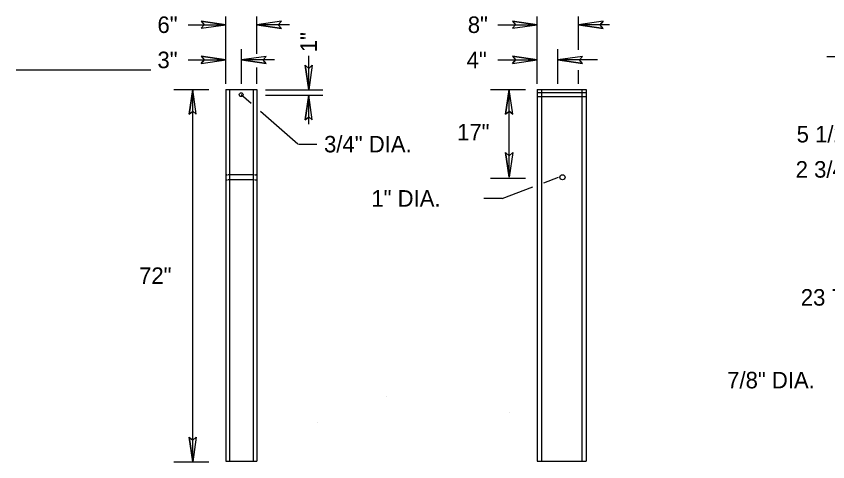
# Model space of a CAD drawing. Extents: x 12.2 to 54.5, y -7.8 to 16.1.
# Drawn here: x 12.24 to 15.188, y 8.946 to 10.565 of the extents above; entities that cross this region are included whole.
import ezdxf

# ---------------------------------------------------------------- set-up
doc = ezdxf.new("R2010")
doc.units = 0
for name, color, linetype in [('BORD-LINE', 7, 'Continuous'), ('DETAIL DIM', 7, 'Continuous'), ('DETL-DIMS', 7, 'Continuous'), ('DETL-LINE', 7, 'Continuous'), ('DETL-NOTE', 7, 'Continuous'), ('DETL-TITL', 7, 'Continuous')]:
    doc.layers.add(name, color=color, linetype=linetype)

msp = doc.modelspace()

# ---------------------------------------------------------------- linework, layer by layer
at = {"layer": 'BORD-LINE'}
for p, q in [((12.7289, 10.3692), (12.2403, 10.3692)), ((13.0011, 10.2989), (13.0011, 8.9489)), ((13.0011, 10.2989), (13.0082, 10.2989)), ((13.0082, 10.2989), (13.1066, 10.2989)), ((13.0148, 10.2989), (13.0148, 8.9489)), ((13.1008, 10.2989), (13.1008, 8.9489)), ((13.1066, 10.2989), (13.1136, 10.2989)), ((13.1136, 10.2989), (13.1136, 8.9489)), ((14.1326, 10.2989), (14.1326, 8.9489)), ((14.1326, 10.2989), (14.1397, 10.2989)), ((14.1397, 10.2989), (14.2756, 10.2989)), ((14.1483, 10.2989), (14.1483, 8.9489)), ((14.2756, 10.2989), (14.3104, 10.2989)), ((14.2948, 10.2989), (14.2948, 8.9489)), ((14.3104, 10.2989), (14.3104, 8.9489)), ((13.0011, 9.9895), (13.0082, 9.9895)), ((13.0011, 9.9708), (13.0082, 9.9708)), ((13.1066, 9.9895), (13.1136, 9.9895)), ((13.1066, 9.9708), (13.1136, 9.9708)), ((13.0011, 8.9489), (13.0082, 8.9489)), ((13.0082, 8.9489), (13.1066, 8.9489)), ((13.1066, 8.9489), (13.1136, 8.9489)), ((14.1326, 8.9489), (14.1397, 8.9489)), ((14.1397, 8.9489), (14.3104, 8.9489)), ((14.2756, 8.9489), (14.2826, 8.9489))]:
    msp.add_line(p, q, dxfattribs=at)
for centre, radius in [((13.0574, 10.2801), 0.00703), ((14.2242, 9.9801), 0.00937)]:
    msp.add_circle(centre, radius, dxfattribs=at)
for points in [[(14.3103, 10.2872), (14.1326, 10.2872)], [(14.1328, 10.2731), (14.3106, 10.2731)], [(13.0047, 9.9895), (13.0011, 9.9895)], [(13.0011, 9.9708), (13.0047, 9.9708)], [(13.104, 9.9893), (13.0099, 9.9893)], [(13.104, 9.9704), (13.0099, 9.9704)], [(13.1136, 9.9895), (13.1101, 9.9895)], [(13.1101, 9.9708), (13.1136, 9.9708)]]:
    msp.add_open_spline(points, degree=1, dxfattribs=at)
at = {"layer": 'DETAIL DIM'}
for p, q in [((14.1326, 10.3197), (14.1326, 10.5643)), ((14.2826, 10.4435), (14.2826, 10.5643)), ((12.8647, 10.5345), (13.0011, 10.5345)), ((13.2331, 10.5345), (13.1136, 10.5345)), ((13.989, 10.5345), (14.1326, 10.5345)), ((14.3947, 10.5345), (14.2826, 10.5345)), ((14.2076, 10.3197), (14.2076, 10.4459)), ((12.8647, 10.4066), (13.0011, 10.4066)), ((13.1779, 10.4066), (13.0583, 10.4066)), ((13.3024, 10.2974), (13.3024, 10.4215)), ((13.989, 10.4066), (14.1326, 10.4066)), ((14.3511, 10.4066), (14.2076, 10.4066)), ((14.2826, 10.3197), (14.2826, 10.3693)), ((12.8811, 8.9463), (12.8811, 10.2989)), ((14.0308, 9.9801), (14.0308, 10.2989)), ((13.0933, 10.2487), (13.0574, 10.2801)), ((13.3024, 10.1731), (13.3024, 10.2786)), ((13.2628, 10.1006), (13.1272, 10.2191)), ((13.2655, 10.1006), (13.3319, 10.1006))]:
    msp.add_line(p, q, dxfattribs=at)
at = {"layer": 'DETL-DIMS'}
for p, q in [((13.0011, 10.3197), (13.0011, 10.5643)), ((13.1136, 10.4288), (13.1136, 10.5643)), ((12.9115, 10.5477), (13.0011, 10.5345)), ((12.9115, 10.5477), (12.9226, 10.5345)), ((12.9115, 10.5216), (13.0011, 10.5345)), ((12.9115, 10.5216), (12.9226, 10.5345)), ((13.2032, 10.5474), (13.1136, 10.5345)), ((13.2032, 10.5213), (13.1136, 10.5345)), ((13.2032, 10.5474), (13.1921, 10.5345)), ((13.2032, 10.5213), (13.1921, 10.5345)), ((14.043, 10.5477), (14.1326, 10.5345)), ((14.043, 10.5477), (14.0541, 10.5345)), ((14.043, 10.5216), (14.1326, 10.5345)), ((14.043, 10.5216), (14.0541, 10.5345)), ((14.3722, 10.5474), (14.2826, 10.5345)), ((14.3722, 10.5213), (14.2826, 10.5345)), ((14.3722, 10.5474), (14.3611, 10.5345)), ((14.3722, 10.5213), (14.3611, 10.5345)), ((13.0583, 10.3197), (13.0583, 10.4459)), ((12.9115, 10.4198), (13.0011, 10.4066)), ((12.9115, 10.4198), (12.9226, 10.4066)), ((12.9115, 10.3937), (13.0011, 10.4066)), ((12.9115, 10.3937), (12.9226, 10.4066)), ((13.1479, 10.4195), (13.0583, 10.4066)), ((13.1479, 10.3934), (13.0583, 10.4066)), ((13.1479, 10.4195), (13.1368, 10.4066)), ((13.1479, 10.3934), (13.1368, 10.4066)), ((14.043, 10.4198), (14.1326, 10.4066)), ((14.043, 10.4198), (14.0541, 10.4066)), ((14.043, 10.3937), (14.1326, 10.4066)), ((14.043, 10.3937), (14.0541, 10.4066)), ((14.2972, 10.4195), (14.2076, 10.4066)), ((14.2972, 10.3934), (14.2076, 10.4066)), ((14.2972, 10.4195), (14.2861, 10.4066)), ((14.2972, 10.3934), (14.2861, 10.4066)), ((13.1136, 10.3197), (13.1136, 10.3794)), ((13.2892, 10.387), (13.3024, 10.2974)), ((13.2892, 10.387), (13.3024, 10.3759)), ((13.3153, 10.387), (13.3024, 10.2974)), ((13.3153, 10.387), (13.3024, 10.3759)), ((12.8126, 10.2989), (12.9404, 10.2989)), ((12.8679, 10.2093), (12.8811, 10.2989)), ((12.894, 10.2093), (12.8811, 10.2989)), ((13.1453, 10.2974), (13.3536, 10.2974)), ((13.9623, 10.2989), (14.0901, 10.2989)), ((14.0176, 10.2093), (14.0308, 10.2989)), ((14.0437, 10.2093), (14.0308, 10.2989)), ((13.1453, 10.2786), (13.3536, 10.2786)), ((13.2892, 10.189), (13.3024, 10.2786)), ((13.3153, 10.189), (13.3024, 10.2786)), ((12.8679, 10.2093), (12.8811, 10.2204)), ((12.894, 10.2093), (12.8811, 10.2204)), ((13.2892, 10.189), (13.3024, 10.2001)), ((13.3153, 10.189), (13.3024, 10.2001)), ((14.0176, 10.2093), (14.0308, 10.2204)), ((14.0437, 10.2093), (14.0308, 10.2204)), ((14.0176, 10.0697), (14.0308, 9.9801)), ((14.0176, 10.0697), (14.0308, 10.0586)), ((14.0437, 10.0697), (14.0308, 9.9801)), ((14.0437, 10.0697), (14.0308, 10.0586)), ((13.9623, 9.9769), (14.0901, 9.9769)), ((14.1567, 9.9602), (14.2098, 9.9801)), ((14.0053, 9.9034), (14.1161, 9.945)), ((14.0053, 9.9034), (13.9389, 9.9034)), ((12.8679, 9.0359), (12.8811, 8.9463)), ((12.8679, 9.0359), (12.8811, 9.0248)), ((12.894, 9.0359), (12.8811, 8.9463)), ((12.894, 9.0359), (12.8811, 9.0248)), ((12.8126, 8.9463), (12.9404, 8.9463))]:
    msp.add_line(p, q, dxfattribs=at)
for points in [[(12.9115, 10.5216), (13.0011, 10.5345), (12.9115, 10.5477), (12.9226, 10.5345)], [(13.2032, 10.5474), (13.1136, 10.5345), (13.2032, 10.5213), (13.1921, 10.5345)], [(14.043, 10.5216), (14.1326, 10.5345), (14.043, 10.5477), (14.0541, 10.5345)], [(14.3722, 10.5474), (14.2826, 10.5345), (14.3722, 10.5213), (14.3611, 10.5345)], [(12.9115, 10.3937), (13.0011, 10.4066), (12.9115, 10.4198), (12.9226, 10.4066)], [(13.1479, 10.4195), (13.0583, 10.4066), (13.1479, 10.3934), (13.1368, 10.4066)], [(14.043, 10.3937), (14.1326, 10.4066), (14.043, 10.4198), (14.0541, 10.4066)], [(14.2972, 10.4195), (14.2076, 10.4066), (14.2972, 10.3934), (14.2861, 10.4066)], [(13.3153, 10.387), (13.3024, 10.2974), (13.2892, 10.387), (13.3024, 10.3759)], [(12.894, 10.2093), (12.8811, 10.2989), (12.8679, 10.2093), (12.8811, 10.2204)], [(14.0437, 10.2093), (14.0308, 10.2989), (14.0176, 10.2093), (14.0308, 10.2204)], [(13.3153, 10.189), (13.3024, 10.2786), (13.2892, 10.189), (13.3024, 10.2001)], [(14.0437, 10.0697), (14.0308, 9.9801), (14.0176, 10.0697), (14.0308, 10.0586)], [(12.894, 9.0359), (12.8811, 8.9463), (12.8679, 9.0359), (12.8811, 9.0248)]]:
    msp.add_lwpolyline(points, close=True, dxfattribs=at)
at = {"layer": 'DETL-LINE'}
for p, q in [((13.5841, 9.1822), (13.5841, 9.1822)), ((13.5841, 9.1822), (13.5841, 9.1822)), ((14.0314, 9.1255), (14.0314, 9.1255)), ((14.0314, 9.1255), (14.0314, 9.1255)), ((14.0314, 9.1255), (14.0314, 9.1255)), ((13.3359, 9.0906), (13.3359, 9.0906))]:
    msp.add_line(p, q, dxfattribs=at)
at = {"layer": 'DETL-TITL'}
msp.add_line((15.1843, 10.419), (15.9076, 10.419), dxfattribs=at)

# ---------------------------------------------------------------- texts
at = {"layer": 'DETL-NOTE'}
for s, p in [('6"', (12.7532, 10.5045)), ('8"', (13.8802, 10.5045)), ('3"', (12.7532, 10.3766)), ('4"', (13.8761, 10.3766)), ('17"', (13.8415, 10.1138)), ('5 1/2"', (15.0747, 10.1067)), ('3/4" DIA.', (13.3583, 10.0706)), ('2 3/4"', (15.0712, 9.9788)), ('1" DIA.', (13.5301, 9.8734)), ('72"', (12.6865, 9.5926)), ('23 7/8"', (15.0898, 9.5137)), ('7/8" DIA.', (14.8224, 9.2131))]:
    msp.add_text(s, height=0.06, dxfattribs=at).set_placement(p)
msp.add_text('1"', height=0.06, rotation=90, dxfattribs=at).set_placement((13.3324, 10.4346))

doc.saveas('drawing.dxf')
